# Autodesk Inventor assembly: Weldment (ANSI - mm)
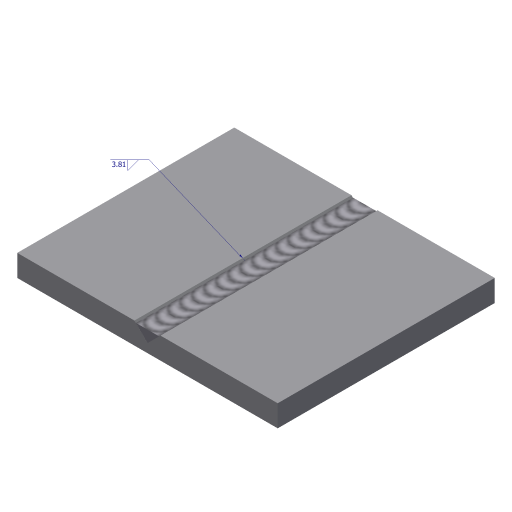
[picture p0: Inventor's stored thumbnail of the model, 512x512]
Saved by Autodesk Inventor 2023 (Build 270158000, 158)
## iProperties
Length Units: 11269
Angle Units: 11283
Time Units: 11279
Mass Units: 11290
Length Display Precision: 3
Angle Display Precision: 2
Part Number: Weldment (ANSI - mm)
Document SubType Name: Weldment
Created: 2002-06
Designer: smithga
Shininess: 64.0
Angle Units: 11279
Time Units: 11290
Mass Units: 11283
Compacted: True
Part Number: fig 16-6
Created: 2003-01
Designer: Owner
Density: 0.0
Volumn: 0.0
Area: 0.0
PropertySet Name: Model Information
Control State: 0
Master: False
Author: Owner
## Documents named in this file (2)
- D:\PROJECTS\Project 2022\Autodesk Inventor For Professional 2023\RESOURCES INVENTOR 2023\RESOURCES INVENTOR 2023\Inventor_2023_Part\Inventor_2023_Part\c16_Inv_2023_prt\fig 16-6\fig 16-6.iam
- D:\PROJECTS\Project 2022\Autodesk Inventor For Professional 2023\RESOURCES INVENTOR 2023\RESOURCES INVENTOR 2023\Inventor_2023_Part\Inventor_2023_Part\c16_Inv_2023_prt\fig 16-6\Part1.ipt
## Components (2 placed, 1 different names)
1. Part1:1 — Mate:1, Flush:1, Flush:2
2. Part1:2 — Mate:1, Flush:1, Flush:2
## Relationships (3: Flush 2, Mate 1)
- Mate:1: Part1:1 ↔ Part1:2
- Flush:1: Part1:1 ↔ Part1:2
- Flush:2: Part1:1 ↔ Part1:2
